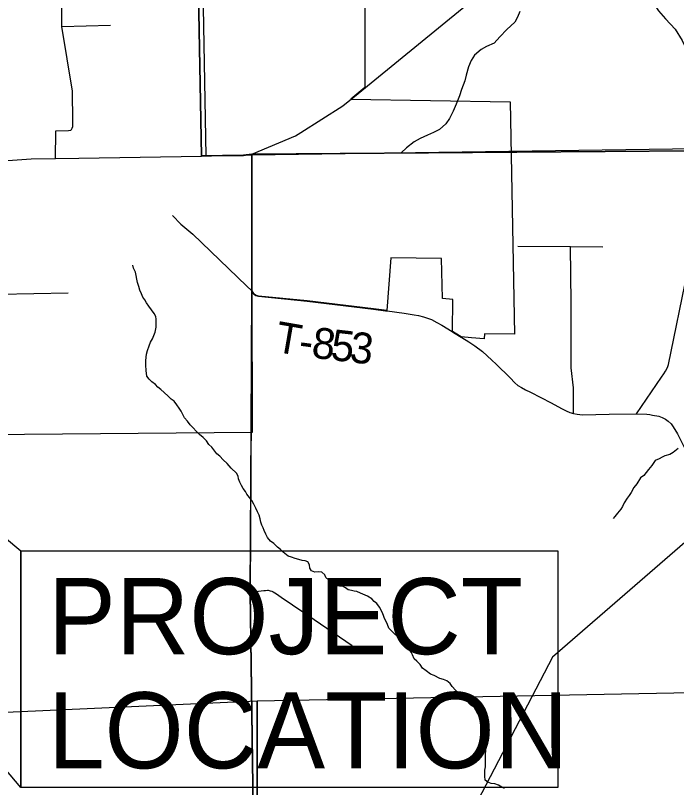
# Model space of a CAD drawing. Extents: x 0 to 34, y 0 to 22.
# Drawn here: x 7.041 to 8.257, y 16.135 to 17.555 of the extents above; entities that cross this region are included whole.
import ezdxf

# ---------------------------------------------------------------- set-up
doc = ezdxf.new("R2010")
doc.units = 0
for name, color, linetype in [('GM_X_City_Street', 7, 'Continuous'), ('GM_X_Corporation', 7, 'Continuous'), ('GM_X_Minor_River', 7, 'Continuous'), ('GM_X_Rail_Line', 7, 'Continuous'), ('GM_X_Section', 7, 'Continuous'), ('GM_X_State_Route', 7, 'Continuous'), ('GM_X_Township', 7, 'Continuous'), ('GM_X_Township_Road', 7, 'Continuous'), ('GM_X_Township_Road_Text', 7, 'Continuous'), ('SH_Cut_Line', 7, 'Continuous'), ('SH_Text', 7, 'Continuous')]:
    doc.layers.add(name, color=color, linetype=linetype)

msp = doc.modelspace()

# ---------------------------------------------------------------- linework, layer by layer
at = {"layer": 'GM_X_City_Street'}
for p, q in [((7.1261, 17.5351), (7.2156, 17.5376)), ((7.1146, 17.2923), (7.1152, 17.3422))]:
    msp.add_line(p, q, dxfattribs=at)
for points in [[(7.1152, 17.3422), (7.1152, 17.3432), (7.1386, 17.3438), (7.1424, 17.3445), (7.1439, 17.3454), (7.1454, 17.348), (7.1464, 17.3514), (7.1466, 17.3604), (7.146, 17.4162), (7.1261, 17.5351), (7.126, 17.5423), (7.1262, 17.7221)], [(7.0107, 17.0427), (7.1377, 17.0454)]]:
    msp.add_lwpolyline(points, dxfattribs=at)
at = {"layer": 'GM_X_Corporation'}
msp.add_lwpolyline([(7.6836, 17.6115), (7.6836, 17.4229), (7.6577, 17.4014), (7.9506, 17.3963), (7.959, 16.9694), (7.9037, 16.9698), (7.903, 16.9608), (7.8795, 16.9625), (7.8607, 16.9644), (7.8446, 16.9741), (7.8451, 17.0327), (7.8263, 17.035), (7.8246, 17.1084), (7.7312, 17.1096), (7.7242, 17.0125), (7.6993, 17.0157), (7.5772, 17.0304), (7.4878, 17.0394), (7.4825, 17.0407), (7.4793, 17.0435), (7.4757, 17.0495), (7.4761, 16.7884), (6.9868, 16.7843)], dxfattribs=at)
at = {"layer": 'GM_X_Minor_River'}
for points in [[(7.9683, 17.5625), (7.9643, 17.5526), (7.9592, 17.543), (7.9446, 17.5298), (7.9315, 17.5159), (7.9211, 17.5044), (7.9075, 17.4984), (7.8974, 17.4929), (7.885, 17.4825), (7.8791, 17.4725), (7.874, 17.461), (7.87, 17.4458), (7.8672, 17.4351), (7.8614, 17.4194), (7.8574, 17.4076), (7.8516, 17.3923), (7.8461, 17.3797), (7.8395, 17.3659), (7.8324, 17.3559), (7.8208, 17.3458), (7.8099, 17.3403), (7.7986, 17.3352), (7.7854, 17.3293), (7.7741, 17.323), (7.7603, 17.3118), (7.7502, 17.3029)], [(7.5816, 16.5447), (7.5784, 16.5504), (7.5735, 16.5522), (7.5682, 16.5532), (7.5621, 16.555), (7.5552, 16.5567), (7.5487, 16.5592), (7.5422, 16.561), (7.533, 16.568), (7.5283, 16.5732), (7.5229, 16.5777), (7.516, 16.5844), (7.5098, 16.5884), (7.5044, 16.5955), (7.5012, 16.6012), (7.4985, 16.6079), (7.4964, 16.6132), (7.4941, 16.6181), (7.4924, 16.6234), (7.4912, 16.6295), (7.4888, 16.6362), (7.486, 16.6426), (7.4828, 16.6494), (7.4793, 16.6566), (7.4753, 16.6633), (7.4714, 16.6686), (7.4664, 16.6749), (7.464, 16.6798), (7.4597, 16.6854), (7.4566, 16.6911), (7.4538, 16.6967), (7.451, 16.7031), (7.4502, 16.708), (7.4474, 16.7137), (7.4377, 16.723), (7.43, 16.7315), (7.423, 16.7382), (7.4168, 16.7446), (7.4114, 16.749), (7.4021, 16.7613), (7.3963, 16.7662), (7.392, 16.7729), (7.3858, 16.7789), (7.3796, 16.7844), (7.3738, 16.7904), (7.3672, 16.7975), (7.3622, 16.8027), (7.3571, 16.809), (7.3517, 16.8154), (7.3454, 16.8274), (7.3419, 16.8334), (7.3376, 16.839), (7.3329, 16.8458), (7.3275, 16.8498), (7.3213, 16.8558), (7.3082, 16.8677), (7.3024, 16.8717), (7.2982, 16.8766), (7.2916, 16.8818), (7.2866, 16.8862), (7.2827, 16.8918), (7.281, 16.9024), (7.2804, 16.9119), (7.2806, 16.9207), (7.2819, 16.9325), (7.2836, 16.939), (7.2865, 16.9478), (7.2894, 16.9543), (7.2926, 16.9605), (7.2951, 16.967), (7.2977, 16.9732), (7.2994, 16.9823), (7.2998, 16.9968), (7.299, 17.0017), (7.2962, 17.007), (7.2911, 17.0141), (7.2861, 17.0208), (7.2818, 17.0268), (7.2786, 17.0321), (7.2751, 17.0373), (7.2727, 17.0437), (7.2696, 17.0501), (7.2679, 17.0569), (7.2655, 17.0645), (7.2613, 17.0834), (7.2581, 17.0909), (7.2569, 17.0959)], [(8.2598, 16.7587), (8.2509, 16.7513), (8.2445, 16.7477), (8.2355, 16.7452), (8.2306, 16.7428), (8.225, 16.7397), (8.2178, 16.7368), (8.2112, 16.7279), (8.2053, 16.7206), (8.1964, 16.7094), (8.1905, 16.7051), (8.1839, 16.6939), (8.1783, 16.6873), (8.1732, 16.6777), (8.1699, 16.6727), (8.1659, 16.6676), (8.1607, 16.6588), (8.1575, 16.6522), (8.1545, 16.6472), (8.1482, 16.6402), (8.1434, 16.634), (8.1403, 16.6303)], [(7.9406, 16.1333), (7.9356, 16.1362), (7.9294, 16.1395), (7.9226, 16.142), (7.9157, 16.1426), (7.91, 16.1451), (7.905, 16.1488), (7.9041, 16.156), (7.904, 16.1617), (7.9042, 16.1675), (7.9053, 16.1736), (7.9055, 16.1789), (7.9057, 16.1892), (7.9055, 16.196), (7.9058, 16.2036), (7.9055, 16.2139), (7.9062, 16.2188), (7.9061, 16.2242), (7.9056, 16.231), (7.9018, 16.2469), (7.8994, 16.2525), (7.897, 16.2608), (7.8915, 16.271), (7.8879, 16.2777), (7.8844, 16.283), (7.8783, 16.287), (7.8697, 16.296), (7.8613, 16.3019), (7.8551, 16.3093), (7.85, 16.3146), (7.8442, 16.3209), (7.8407, 16.3269), (7.8345, 16.3313), (7.8284, 16.3338), (7.8216, 16.3356), (7.8112, 16.3411), (7.804, 16.344), (7.7963, 16.3502), (7.7897, 16.355), (7.785, 16.3614), (7.7792, 16.3677), (7.7742, 16.3718), (7.7714, 16.3794), (7.7687, 16.3842), (7.7651, 16.3895), (7.7604, 16.3977), (7.7527, 16.4033), (7.7461, 16.4126), (7.74, 16.4163), (7.7276, 16.4282), (7.7252, 16.435), (7.7228, 16.4406), (7.7196, 16.4463), (7.718, 16.4516), (7.7152, 16.4576), (7.7105, 16.467), (7.7054, 16.4737), (7.7004, 16.4778), (7.6962, 16.4826), (7.6885, 16.4874), (7.6755, 16.4928), (7.669, 16.4957), (7.664, 16.4964), (7.6587, 16.4978), (7.6526, 16.4992), (7.6476, 16.5025), (7.6423, 16.5058), (7.637, 16.5057), (7.6297, 16.5063), (7.6236, 16.5107), (7.617, 16.5166), (7.612, 16.5218), (7.6096, 16.5267), (7.6046, 16.5316), (7.5989, 16.5322), (7.5913, 16.5317), (7.5852, 16.5342), (7.5825, 16.5391), (7.5816, 16.5447)]]:
    msp.add_lwpolyline(points, dxfattribs=at)
at = {"layer": 'GM_X_Rail_Line'}
for points in [[(5.5102, 20.2613), (5.523, 19.2739), (5.5231, 19.2652), (5.5475, 19.2638), (5.6176, 19.2598), (5.6417, 19.2587), (5.7517, 19.2562), (5.8416, 19.2572), (5.9232, 19.2589), (5.975, 19.26), (6.1325, 19.2626), (6.1415, 19.2628), (6.1868, 19.2635), (6.2112, 19.2639), (6.3582, 19.2663), (6.8468, 19.2759), (7.2763, 19.2784), (7.3458, 19.2789), (7.3701, 17.9909), (7.3831, 17.2974), (7.46, 17.2982), (7.4754, 17.3006), (8.2882, 17.3064)], [(8.3593, 16.6612), (8.0289, 16.3753), (7.8223, 15.9782), (7.5545, 15.6879), (7.4125, 15.5332), (7.3528, 15.4637), (7.2999, 15.4014), (7.2245, 15.3226)]]:
    msp.add_lwpolyline(points, dxfattribs=at)
msp.add_lwpolyline([(5.5619, 14.1), (8.9, 14.1), (8.9, 17.3138), (8.2882, 17.3064), (7.4754, 17.3006), (7.4757, 17.0495), (7.4723, 16.4951), (7.4818, 15.827), (7.482, 15.8179), (7.4834, 15.2992), (7.3416, 15.297), (6.5709, 15.2859), (6.3575, 15.2833), (5.5569, 15.2761), (5.5579, 15.2049), (5.5588, 15.1747), (5.5581, 14.9676), (5.5583, 14.9347), (5.5595, 14.6439), (5.5615, 14.2414), (5.5608, 14.205)], close=True, dxfattribs=at)
at = {"layer": 'GM_X_Section'}
for points in [[(7.3737, 18.2882), (8.3698, 18.3026), (8.3784, 17.3112), (7.4756, 17.2983), (7.3918, 17.2975)], [(7.4857, 16.2946), (8.4434, 16.3129), (8.4501, 15.3065), (7.4868, 15.3017)], [(6.5053, 16.2508), (7.4857, 16.2946), (7.4868, 15.3017), (6.5184, 15.2893)]]:
    msp.add_lwpolyline(points, close=True, dxfattribs=at)
at = {"layer": 'GM_X_State_Route'}
msp.add_line((7.6714, 17.4122), (7.702, 17.4373), dxfattribs=at)
for points in [[(7.702, 17.4373), (7.943, 17.6347), (7.9769, 17.6625)], [(7.5657, 17.3403), (7.6431, 17.389), (7.6714, 17.4122)], [(7.4756, 17.3001), (7.5557, 17.334), (7.5657, 17.3403)], [(7.4015, 17.2971), (7.4602, 17.2977), (7.4756, 17.3001)], [(6.9135, 17.281), (7.0694, 17.2919), (7.1146, 17.2923), (7.1571, 17.293)], [(7.1571, 17.293), (7.3833, 17.2969), (7.4015, 17.2971)]]:
    msp.add_lwpolyline(points, dxfattribs=at)
at = {"layer": 'GM_X_Township'}
msp.add_lwpolyline([(6.3582, 19.2663), (6.8468, 19.2759), (7.2763, 19.2784), (7.3458, 19.2789), (7.3701, 17.9909), (7.3831, 17.2974), (7.46, 17.2982), (7.4754, 17.3006), (7.4757, 17.0495), (7.4723, 16.4951), (7.4818, 15.827), (7.482, 15.8179), (7.4834, 15.2992)], dxfattribs=at)
at = {"layer": 'GM_X_Township_Road'}
for p, q in [((7.4756, 17.2711), (7.4756, 17.3001)), ((7.4759, 17.0489), (7.4756, 17.2711)), ((7.4744, 16.797), (7.4759, 17.0489))]:
    msp.add_line(p, q, dxfattribs=at)
for points in [[(8.1999, 17.635), (8.1999, 17.6177), (8.2024, 17.6018), (8.21, 17.5833), (8.2236, 17.5641), (8.2368, 17.5495), (8.2543, 17.53), (8.2672, 17.5093), (8.2777, 17.4874), (8.2804, 17.4715), (8.2846, 17.4491), (8.2887, 17.4097), (8.2884, 17.3058)], [(8.1834, 16.8228), (8.2289, 16.8904), (8.2334, 16.8961), (8.2367, 16.9011), (8.239, 16.9053), (8.2408, 16.9097), (8.2418, 16.9133), (8.2771, 17.0838), (8.2795, 17.0956), (8.2874, 17.1388), (8.2907, 17.1603), (8.2914, 17.1653), (8.2917, 17.1711), (8.2916, 17.177), (8.2906, 17.1902), (8.2888, 17.2353), (8.2886, 17.2721), (8.2884, 17.3058)], [(7.3296, 17.1878), (7.3453, 17.1716), (7.3671, 17.1531), (7.4658, 17.0583), (7.4759, 17.0489)], [(7.9652, 17.1309), (8.0617, 17.1302), (8.1215, 17.1298)], [(8.0672, 16.8234), (8.0671, 16.8708), (8.0629, 16.9073), (8.0629, 17.0271), (8.0617, 17.1302)], [(7.4759, 17.0489), (7.4795, 17.043), (7.4827, 17.0402), (7.488, 17.0389), (7.5774, 17.0298), (7.6995, 17.0152), (7.7214, 17.0124)], [(7.7214, 17.0124), (7.7244, 17.012), (7.7558, 17.0079), (7.7743, 17.005), (7.7824, 17.0037), (7.7913, 17.0014), (7.7988, 16.9987), (7.8062, 16.9959), (7.816, 16.9908), (7.8253, 16.9857), (7.844, 16.9741)], [(7.844, 16.9741), (7.8448, 16.9736), (7.8468, 16.9724), (7.8609, 16.9639), (7.8617, 16.9634)], [(7.8617, 16.9634), (7.875, 16.9553), (7.886, 16.9475), (7.8997, 16.9371), (7.9173, 16.9212), (7.9252, 16.9141), (7.9508, 16.8888), (7.9593, 16.8798), (7.9651, 16.8751), (7.9714, 16.8713), (7.9789, 16.867), (7.9885, 16.8626), (8.0265, 16.843), (8.0455, 16.8324), (8.054, 16.8282), (8.0606, 16.8253), (8.0672, 16.8234), (8.0742, 16.8218), (8.0836, 16.821), (8.1328, 16.822), (8.1834, 16.8228)], [(8.1834, 16.8228), (8.202, 16.822), (8.2077, 16.8214), (8.2128, 16.8204), (8.2245, 16.8183), (8.2305, 16.816), (8.2364, 16.8131), (8.2416, 16.8093), (8.2468, 16.8042), (8.2508, 16.7988), (8.2589, 16.786), (8.268, 16.7675), (8.2735, 16.7562), (8.2775, 16.7505), (8.2827, 16.745), (8.2908, 16.7384), (8.3127, 16.728), (8.4034, 16.6946), (8.431, 16.6848), (8.4391, 16.6814), (8.4462, 16.6768)], [(7.4801, 15.8119), (7.4822, 15.8174), (7.482, 15.8265), (7.4725, 16.4946), (7.4744, 16.797)], [(7.4725, 16.4946), (7.4979, 16.4977), (7.501, 16.498), (7.5043, 16.4982), (7.5056, 16.4982), (7.5076, 16.4979), (7.5094, 16.4974), (7.5121, 16.4965), (7.5149, 16.4953), (7.5177, 16.4937), (7.5207, 16.4916), (7.5298, 16.4853), (7.5903, 16.4442), (7.6603, 16.3965)]]:
    msp.add_lwpolyline(points, dxfattribs=at)
at = {"layer": 'SH_Cut_Line'}
for points in [[(6.3582, 19.2663), (6.8468, 19.2759), (7.2763, 19.2784), (7.3458, 19.2789), (7.3701, 17.9909), (7.3831, 17.2974), (7.46, 17.2982), (7.4754, 17.3006), (8.2882, 17.3064)], [(8.2882, 17.3064), (7.4754, 17.3006), (7.46, 17.2982), (7.3831, 17.2974), (7.3701, 17.9909), (7.3458, 19.2789), (7.2763, 19.2784), (6.8468, 19.2759), (6.3582, 19.2663)]]:
    msp.add_lwpolyline(points, dxfattribs=at)
at = {"layer": 'SH_Text'}
for points in [[(5.8041, 17.6143), (7.0506, 16.5706), (7.0506, 16.1356)], [(7.0506, 16.5706), (8.0387, 16.5706), (8.0387, 16.1356), (7.0506, 16.1356)], [(7.0506, 16.5706), (8.0387, 16.5706), (8.0387, 16.1356), (7.0506, 16.1356)], [(7.0506, 16.5706), (8.0387, 16.5706), (8.0387, 16.1356), (7.0506, 16.1356)]]:
    msp.add_lwpolyline(points, close=True, dxfattribs=at)

# ---------------------------------------------------------------- texts
at = {"layer": 'GM_X_Township_Road_Text'}
for s, rotation, p in [('T', 350.1544, (7.5158, 16.9373)), ('8', 352.9118, (7.5838, 16.9264)), ('5', 353.4107, (7.619, 16.9221)), ('3', 353.5249, (7.6539, 16.918)), ('-', 352.3301, (7.56, 16.9296))]:
    msp.add_text(s, height=0.0568, rotation=rotation, dxfattribs=at).set_placement(p)
at = {"layer": 'SH_Text'}
for s, p in [('PROJECT', (7.1006, 16.3806)), ('LOCATION', (7.1006, 16.1706))]:
    msp.add_text(s, height=0.14, dxfattribs=at).set_placement(p)

doc.saveas('drawing.dxf')
